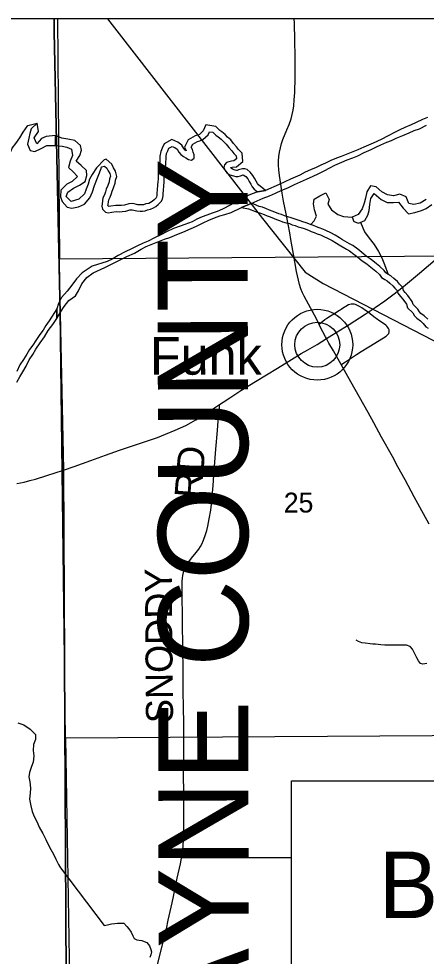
# Model space of a CAD drawing. Extents: x 0 to 34, y 0 to 22.
# Drawn here: x 2.529 to 3.385, y 18.929 to 20.9 of the extents above; entities that cross this region are included whole.
import ezdxf

# ---------------------------------------------------------------- set-up
doc = ezdxf.new("R2010")
doc.units = 0
for name, color, linetype in [('Default', 7, 'Continuous'), ('GM_X_County_Road', 7, 'Continuous'), ('GM_X_County_Text', 7, 'Continuous'), ('GM_X_Major_River', 7, 'Continuous'), ('GM_X_Minor_River', 7, 'Continuous'), ('GM_X_Rail_Line', 7, 'Continuous'), ('GM_X_Section', 7, 'Continuous'), ('GM_X_Section_Text', 7, 'Continuous'), ('GM_X_State_Route', 7, 'Continuous'), ('GM_X_Township_Road', 7, 'Continuous'), ('GM_X_Township_Road_Text', 7, 'Continuous'), ('GM_X_Unincorporated', 7, 'Continuous'), ('GM_X_Unincorporated_Location', 7, 'Continuous'), ('GM_X_Unincorporated_Text', 7, 'Continuous'), ('SH_Cut_Line', 7, 'Continuous'), ('SH_Text', 7, 'Continuous')]:
    doc.layers.add(name, color=color, linetype=linetype)

msp = doc.modelspace()

# ---------------------------------------------------------------- linework, layer by layer
at = {"layer": 'Default'}
for points in [[(2.6032, 20.9), (2.1, 20.9), (2.1, 18.375), (2.6118, 18.3803), (2.6161, 18.3799), (2.6204, 18.3797), (2.6263, 18.3795), (2.6292, 18.3794), (2.6281, 18.8843), (2.6224, 19.9515), (2.6032, 20.8721)], [(3.6061, 20.9), (2.6099, 20.9), (2.614, 20.3953), (3.6114, 20.403), (3.6121, 20.4224)]]:
    msp.add_lwpolyline(points, close=True, dxfattribs=at)
msp.add_lwpolyline([(8.9, 20.9), (2.6032, 20.9), (2.6032, 20.8721), (2.6224, 19.9515), (2.6281, 18.8843)], dxfattribs=at)
at = {"layer": 'GM_X_County_Road'}
for points in [[(3.16, 20.2571), (3.1544, 20.2691), (3.1336, 20.3074), (3.1286, 20.3164), (3.1252, 20.3239), (3.1217, 20.3323), (3.1187, 20.3412), (3.1165, 20.3502), (3.1129, 20.3684), (3.1065, 20.4051), (3.1008, 20.4358), (3.0982, 20.45), (3.0947, 20.4681), (3.0906, 20.4899), (3.0882, 20.5028), (3.0855, 20.5162), (3.0826, 20.5335), (3.077, 20.5704), (3.0755, 20.5824), (3.0749, 20.5918), (3.0749, 20.6011), (3.0754, 20.6104), (3.0767, 20.6196), (3.0786, 20.6286), (3.081, 20.6376), (3.0841, 20.6463), (3.0924, 20.6663), (3.0972, 20.6779), (3.1011, 20.6897), (3.1036, 20.6988), (3.1055, 20.7079), (3.1069, 20.7172), (3.108, 20.7296), (3.1089, 20.7452), (3.1098, 20.7763), (3.1096, 20.8074), (3.1096, 20.8229), (3.1095, 20.8335), (3.1093, 20.8418), (3.1091, 20.8519), (3.109, 20.8603), (3.1085, 20.885), (3.1082, 20.891), (3.108, 20.9)], [(3.1755, 20.2275), (3.1734, 20.2311), (3.1681, 20.2419), (3.1623, 20.2524), (3.16, 20.2571)], [(3.2065, 20.1729), (3.1903, 20.2018), (3.1807, 20.2179), (3.1755, 20.2275)], [(3.3915, 19.8376), (3.372, 19.8729), (3.3601, 19.8947), (3.3409, 19.9303), (3.3259, 19.9577), (3.3141, 19.9794), (3.2914, 20.0201), (3.2751, 20.0501), (3.2633, 20.0718), (3.2453, 20.1043), (3.2271, 20.1368), (3.207, 20.1719), (3.2065, 20.1729)]]:
    msp.add_lwpolyline(points, dxfattribs=at)
at = {"layer": 'GM_X_Major_River'}
for points in [[(3.3878, 20.692), (3.3776, 20.6882), (3.364, 20.682), (3.3538, 20.6771), (3.3406, 20.6713), (3.3296, 20.6663), (3.3183, 20.661), (3.305, 20.6541), (3.2907, 20.6461), (3.274, 20.6384), (3.2642, 20.6342), (3.254, 20.63), (3.2415, 20.6242), (3.2275, 20.6185), (3.2173, 20.6146), (3.2063, 20.6104), (3.1965, 20.6066), (3.1851, 20.602), (3.1738, 20.5966), (3.164, 20.592), (3.1538, 20.5871), (3.142, 20.5825), (3.1307, 20.5771), (3.1197, 20.5714), (3.1095, 20.5671), (3.0997, 20.5625), (3.0883, 20.5568), (3.0759, 20.5514), (3.0474, 20.539)], [(3.2896, 20.6347), (3.3024, 20.6408), (3.3123, 20.6443), (3.3221, 20.6489), (3.3361, 20.6546), (3.3497, 20.66), (3.3603, 20.665), (3.3713, 20.6688), (3.386, 20.6761)], [(3.0173, 20.5118), (3.0302, 20.5171), (3.0426, 20.5225), (3.0559, 20.5278), (3.0684, 20.5336), (3.082, 20.5393), (3.0941, 20.5443), (3.1081, 20.5512), (3.1213, 20.557), (3.1334, 20.5627), (3.1478, 20.5688), (3.158, 20.5738), (3.1708, 20.5803), (3.1825, 20.5864), (3.1935, 20.5922), (3.2079, 20.5983), (3.2192, 20.6033), (3.231, 20.6079), (3.2415, 20.6117), (3.2548, 20.6186), (3.2699, 20.6251), (3.2797, 20.6301), (3.2896, 20.6347)], [(3.0474, 20.539), (3.0305, 20.5359)], [(3.0305, 20.5359), (3.0123, 20.5288), (2.9998, 20.523), (2.9847, 20.515), (2.9745, 20.5089), (2.9571, 20.4997), (2.9458, 20.4947), (2.9352, 20.4909), (2.9242, 20.4867), (2.9144, 20.4836), (2.903, 20.4786), (2.8932, 20.4729), (2.8781, 20.4671), (2.8682, 20.4637), (2.8542, 20.4591), (2.8406, 20.4529), (2.8274, 20.4457), (2.8142, 20.4392), (2.8005, 20.4327), (2.7903, 20.4281), (2.7771, 20.4219), (2.7654, 20.4162), (2.7525, 20.4101), (2.7374, 20.4024), (2.7249, 20.3948), (2.7147, 20.3898)], [(2.7098, 20.3769), (2.7208, 20.3823), (2.7337, 20.3888), (2.7458, 20.3953), (2.7556, 20.3999), (2.7719, 20.4071), (2.7858, 20.4152), (2.7964, 20.4209), (2.8104, 20.4266), (2.821, 20.4312), (2.835, 20.4366), (2.846, 20.4401), (2.8607, 20.4462), (2.8736, 20.4516), (2.8914, 20.4589), (2.9023, 20.4642), (2.9163, 20.4711), (2.9284, 20.4765), (2.9401, 20.4811), (2.9515, 20.4853), (2.9617, 20.4884), (2.9749, 20.4926), (2.9971, 20.5032)], [(2.9971, 20.5032), (3.0173, 20.5118)], [(2.7147, 20.3898), (2.683, 20.3797), (2.6724, 20.3725), (2.6622, 20.366), (2.6501, 20.3534), (2.6403, 20.3401), (2.6305, 20.3275), (2.6185, 20.3138), (2.6122, 20.3011), (2.6085, 20.2898)], [(2.6086, 20.2698), (2.6167, 20.283), (2.6238, 20.2952), (2.634, 20.3074), (2.648, 20.3177), (2.654, 20.328), (2.6611, 20.3424), (2.6717, 20.3561), (2.6853, 20.3661), (2.7098, 20.3769)], [(2.6085, 20.2898), (2.6086, 20.2698)]]:
    msp.add_lwpolyline(points, dxfattribs=at)
at = {"layer": 'GM_X_Minor_River'}
for points in [[(2.3836, 20.5154), (2.3901, 20.5192), (2.3999, 20.5207), (2.4128, 20.528), (2.4188, 20.5382), (2.4241, 20.5512), (2.4275, 20.5622), (2.4347, 20.5743), (2.4434, 20.5846), (2.4555, 20.5964), (2.4695, 20.6036), (2.4812, 20.5999), (2.4945, 20.5984), (2.5047, 20.6064), (2.5096, 20.6163), (2.5149, 20.6277), (2.5221, 20.6376), (2.5308, 20.6494), (2.5376, 20.6615), (2.5478, 20.6752), (2.567, 20.6805)], [(2.567, 20.6805), (2.555, 20.6684), (2.552, 20.6589), (2.5498, 20.649), (2.5471, 20.6361), (2.5525, 20.6229), (2.5624, 20.6206), (2.5756, 20.6271), (2.5877, 20.6336), (2.606, 20.6337)], [(2.6058, 20.6545), (2.5862, 20.6522), (2.5763, 20.648), (2.5669, 20.6373), (2.5611, 20.6495), (2.5698, 20.6628), (2.567, 20.6805)], [(3.0041, 20.5843), (2.9987, 20.5845), (2.9906, 20.582), (2.988, 20.5812), (2.9865, 20.5812), (2.9836, 20.5818), (2.9779, 20.5837), (2.975, 20.5857), (2.974, 20.587), (2.9776, 20.5878), (2.9864, 20.5884), (2.9997, 20.6), (2.9985, 20.6173), (2.9908, 20.625), (2.9866, 20.6307), (2.9798, 20.6374), (2.9744, 20.6452), (2.9678, 20.6512), (2.9625, 20.6564), (2.9555, 20.6621), (2.9511, 20.6651), (2.9429, 20.6733), (2.9217, 20.6766), (2.9163, 20.664), (2.9126, 20.6608), (2.9085, 20.6569), (2.9048, 20.6553), (2.8992, 20.6536), (2.8845, 20.6456), (2.8772, 20.6298), (2.8807, 20.6223), (2.8783, 20.624), (2.8759, 20.6269), (2.8717, 20.6341), (2.8633, 20.6406), (2.8502, 20.6458), (2.8346, 20.637), (2.83, 20.6277), (2.827, 20.6206), (2.8255, 20.6112), (2.8255, 20.6052), (2.8252, 20.5991), (2.8252, 20.5946), (2.8247, 20.5905), (2.8223, 20.5833), (2.8219, 20.5747), (2.8216, 20.5679), (2.8216, 20.5629), (2.8213, 20.5569), (2.8206, 20.5509), (2.8199, 20.5396), (2.8191, 20.5338), (2.8191, 20.5293), (2.8183, 20.5252), (2.8174, 20.5235), (2.8132, 20.5193), (2.8088, 20.5158), (2.8053, 20.5133), (2.8018, 20.5118), (2.7956, 20.5107), (2.7909, 20.5088), (2.7876, 20.5084), (2.7843, 20.5084), (2.7793, 20.5089), (2.7682, 20.5114), (2.7597, 20.5108), (2.7509, 20.5083), (2.7446, 20.5074), (2.7395, 20.507), (2.7326, 20.5074), (2.7223, 20.506), (2.7177, 20.5051), (2.7163, 20.5064), (2.7162, 20.5068), (2.7166, 20.5094), (2.7173, 20.5149), (2.718, 20.5194), (2.7205, 20.5246), (2.7236, 20.5324), (2.7247, 20.5377), (2.7277, 20.5447), (2.7314, 20.554), (2.7321, 20.5607), (2.7347, 20.5681), (2.7323, 20.5794), (2.7281, 20.5864), (2.7245, 20.5941), (2.7121, 20.6044), (2.708, 20.6033)], [(2.7017, 20.5848), (2.7023, 20.5883), (2.7091, 20.5902), (2.714, 20.586), (2.7167, 20.5803), (2.7202, 20.5747), (2.7213, 20.569), (2.7195, 20.5636), (2.7187, 20.5572), (2.7157, 20.5495), (2.7124, 20.5415), (2.7113, 20.5362), (2.7086, 20.5297), (2.7056, 20.5233), (2.7045, 20.5168), (2.7038, 20.5111), (2.7031, 20.5058), (2.705, 20.4993), (2.7111, 20.4936), (2.7164, 20.4917), (2.7244, 20.4933), (2.7331, 20.4945), (2.7396, 20.4941), (2.746, 20.4945), (2.7536, 20.4957), (2.7619, 20.498), (2.7672, 20.4984), (2.7771, 20.4962), (2.7836, 20.4955), (2.7885, 20.4955), (2.7942, 20.4963), (2.7991, 20.4982), (2.8056, 20.4994), (2.8116, 20.5021), (2.8165, 20.5055), (2.8218, 20.5097), (2.8279, 20.5158), (2.8305, 20.5208), (2.832, 20.528), (2.832, 20.533), (2.8327, 20.5383), (2.8334, 20.5497), (2.8341, 20.5558), (2.8345, 20.5626), (2.8344, 20.5676), (2.8348, 20.574), (2.8351, 20.5809), (2.8374, 20.5877), (2.8381, 20.5938), (2.8381, 20.5988), (2.8384, 20.6049), (2.8384, 20.6102), (2.8395, 20.617), (2.8417, 20.6224), (2.8444, 20.6277), (2.8512, 20.6315), (2.8569, 20.6293), (2.8618, 20.6255), (2.8653, 20.6194), (2.8695, 20.6145), (2.8752, 20.6103), (2.8801, 20.6077), (2.8855, 20.6043), (2.8919, 20.6028), (2.8976, 20.607), (2.8972, 20.6139), (2.8956, 20.6196), (2.8937, 20.6249), (2.8914, 20.6298), (2.8944, 20.6363), (2.9043, 20.6417), (2.9092, 20.6432), (2.9156, 20.6459), (2.9213, 20.6512), (2.9269, 20.6562), (2.9296, 20.6623), (2.9368, 20.6612), (2.9429, 20.6551), (2.9478, 20.6517), (2.9539, 20.6468), (2.9589, 20.6419), (2.9646, 20.6366), (2.97, 20.629), (2.9768, 20.6222), (2.981, 20.6165), (2.986, 20.6116), (2.9864, 20.6055), (2.9811, 20.601), (2.9758, 20.6005), (2.9701, 20.5994), (2.9652, 20.5975), (2.9611, 20.5925), (2.9599, 20.5872), (2.9623, 20.5811), (2.9661, 20.5762), (2.9722, 20.572), (2.9802, 20.5694), (2.9851, 20.5683), (2.99, 20.5683), (2.995, 20.5698), (3.0006, 20.5721)], [(2.606, 20.6337), (2.6058, 20.6545)], [(2.708, 20.6033), (2.6917, 20.5868), (2.6826, 20.5723), (2.6773, 20.5628), (2.6744, 20.5521), (2.6706, 20.5419), (2.6665, 20.532), (2.6548, 20.5205), (2.6389, 20.5159), (2.6286, 20.5261), (2.6316, 20.5357), (2.6437, 20.5437), (2.6562, 20.5502), (2.6683, 20.5578), (2.672, 20.5707), (2.6712, 20.581), (2.6598, 20.5916), (2.6495, 20.6007), (2.6571, 20.6125), (2.6604, 20.6239), (2.6581, 20.6337), (2.6464, 20.644), (2.6319, 20.6469), (2.6194, 20.6488), (2.6058, 20.6545)], [(2.606, 20.6337), (2.6199, 20.6321), (2.6294, 20.6298), (2.6392, 20.6261), (2.6415, 20.6128), (2.637, 20.6006), (2.6333, 20.5869), (2.6428, 20.5779), (2.6523, 20.568), (2.6406, 20.5581), (2.6297, 20.552), (2.6172, 20.5394), (2.6161, 20.5253), (2.6196, 20.5155), (2.6306, 20.5037), (2.6405, 20.5015), (2.6541, 20.5042), (2.6666, 20.51), (2.6783, 20.5233), (2.6839, 20.5358), (2.6876, 20.5495), (2.7017, 20.5848)], [(3.0474, 20.539), (3.0327, 20.5506), (3.0304, 20.5536), (3.028, 20.5587), (3.0242, 20.5645), (3.0207, 20.5705), (3.0149, 20.5773), (3.0088, 20.5827), (3.0041, 20.5843)], [(3.0006, 20.5721), (3.006, 20.568), (3.0102, 20.5631), (3.0132, 20.5578), (3.0167, 20.5524), (3.0194, 20.5468), (3.0236, 20.5415), (3.0305, 20.5359)], [(3.0305, 20.5359), (3.0474, 20.539)], [(3.3855, 20.5199), (3.3723, 20.5122), (3.3595, 20.5091), (3.3485, 20.5117), (3.3431, 20.5257), (3.3298, 20.5309), (3.3166, 20.5278), (3.3037, 20.5296), (3.2919, 20.536), (3.2801, 20.5465), (3.2683, 20.5484), (3.2601, 20.5358), (3.2575, 20.5225), (3.2545, 20.5119), (3.2504, 20.5001), (3.2422, 20.4883), (3.2293, 20.4829)], [(3.1419, 20.467), (3.1494, 20.4752), (3.1547, 20.4851), (3.1505, 20.4984), (3.1481, 20.5105), (3.1496, 20.5207), (3.1613, 20.528), (3.1741, 20.5338), (3.181, 20.5198), (3.1784, 20.5103), (3.1864, 20.4982), (3.1997, 20.4884), (3.2115, 20.4843), (3.2295, 20.483)], [(3.2332, 20.4734), (3.2426, 20.4705), (3.2559, 20.4755), (3.2626, 20.4873), (3.2656, 20.4968), (3.2667, 20.5097), (3.2692, 20.5218), (3.2756, 20.5325), (3.2908, 20.5197), (3.3034, 20.5133), (3.3166, 20.5134), (3.3269, 20.5142), (3.3368, 20.5017), (3.3482, 20.49), (3.3614, 20.4928), (3.3751, 20.4967), (3.3853, 20.5009), (3.397, 20.5093)], [(3.0173, 20.5118), (2.9971, 20.5032)], [(2.9971, 20.5032), (3.0113, 20.5003), (3.017, 20.4985), (3.0242, 20.4955), (3.0299, 20.4932), (3.0371, 20.4913), (3.0447, 20.4883), (3.0508, 20.4857), (3.0569, 20.4834), (3.0656, 20.4801), (3.0706, 20.4778), (3.0767, 20.4759), (3.0831, 20.4733), (3.0907, 20.471), (3.0976, 20.4692), (3.1037, 20.4669), (3.1097, 20.465), (3.1162, 20.4628), (3.1219, 20.4609), (3.1284, 20.4587), (3.1375, 20.4553), (3.1432, 20.453), (3.1497, 20.4504), (3.1557, 20.4481), (3.163, 20.4455), (3.1687, 20.4429), (3.179, 20.438), (3.1873, 20.4338), (3.1965, 20.4282), (3.2026, 20.4244), (3.2178, 20.4154), (3.2239, 20.412), (3.2334, 20.4052), (3.2414, 20.3987), (3.2509, 20.3908), (3.2601, 20.3844), (3.2654, 20.3806), (3.2726, 20.3749), (3.2795, 20.3693), (3.2868, 20.3624), (3.291, 20.356), (3.2986, 20.3515), (3.3035, 20.3488), (3.3089, 20.3439), (3.3153, 20.3386), (3.3192, 20.3337), (3.3245, 20.3284), (3.3257, 20.3227), (3.3314, 20.3163), (3.3364, 20.3102), (3.344, 20.2996), (3.3463, 20.2924), (3.3574, 20.2814), (3.3605, 20.2757), (3.3658, 20.2704), (3.373, 20.2651), (3.3791, 20.2595), (3.3845, 20.2523), (3.3894, 20.2496)], [(3.3888, 20.2681), (3.3812, 20.2751), (3.3742, 20.2802), (3.3709, 20.2835), (3.3678, 20.2892), (3.3576, 20.2993), (3.3556, 20.3055), (3.3466, 20.3181), (3.3412, 20.3246), (3.3376, 20.3287), (3.3363, 20.3348), (3.3288, 20.3423), (3.3246, 20.3477), (3.3173, 20.3537), (3.311, 20.3594), (3.3049, 20.3627), (3.3001, 20.3655), (3.2967, 20.3708), (3.288, 20.3789), (3.2807, 20.385), (3.2731, 20.3909), (3.2675, 20.3949), (3.2588, 20.401), (3.2496, 20.4087), (3.2412, 20.4154), (3.2308, 20.4229), (3.2242, 20.4265), (3.2092, 20.4354), (3.2032, 20.4391), (3.1936, 20.4451), (3.1846, 20.4496), (3.1742, 20.4545), (3.1679, 20.4574), (3.1602, 20.4602), (3.1543, 20.4624), (3.148, 20.465), (3.1421, 20.4673), (3.1327, 20.4708), (3.126, 20.4731), (3.1203, 20.475), (3.1138, 20.4773), (3.1078, 20.4791), (3.1015, 20.4815), (3.0943, 20.4834), (3.0874, 20.4855), (3.081, 20.4881), (3.0752, 20.4899), (3.0706, 20.4919), (3.0615, 20.4955), (3.0556, 20.4976), (3.0496, 20.5002), (3.0411, 20.5036), (3.0339, 20.5055), (3.029, 20.5074), (3.0215, 20.5105), (3.0173, 20.5118)], [(3.2293, 20.4829), (3.2332, 20.4734)], [(3.2469, 20.4721), (3.2556, 20.4523), (3.2655, 20.4384), (3.2758, 20.4251), (3.285, 20.4104), (3.2919, 20.3975), (3.2973, 20.3832), (3.3056, 20.3623)], [(2.6085, 20.2898), (2.5922, 20.2648), (2.5858, 20.255), (2.5798, 20.2455), (2.573, 20.2359), (2.5646, 20.2234), (2.5582, 20.2139), (2.5514, 20.2044), (2.5454, 20.1949), (2.5386, 20.1839), (2.531, 20.1721), (2.5243, 20.1584)], [(2.6086, 20.2698), (2.6085, 20.2898)], [(2.5243, 20.136), (2.5311, 20.1474), (2.5372, 20.1577), (2.5439, 20.1695), (2.5507, 20.1831), (2.5579, 20.1938), (2.5647, 20.2056), (2.5738, 20.2185), (2.5825, 20.231), (2.5904, 20.2443), (2.6002, 20.2573), (2.6086, 20.2698)], [(3.3864, 19.5448), (3.3784, 19.5429), (3.373, 19.5448), (3.3688, 19.5501), (3.3654, 19.5562), (3.3592, 19.5691), (3.3562, 19.5745), (3.3516, 19.5802), (3.3435, 19.5828), (3.3378, 19.5828), (3.3302, 19.5832), (3.3248, 19.5829), (3.3184, 19.5832), (3.3123, 19.5829), (3.2985, 19.5829), (3.2901, 19.584), (3.2844, 19.5844), (3.279, 19.5848), (3.2733, 19.5852), (3.2672, 19.5859), (3.2569, 19.5875), (3.25, 19.5878), (3.2432, 19.5905), (3.2382, 19.5932)], [(2.5267, 19.4194), (2.5396, 19.4153), (2.5525, 19.4066), (2.5639, 19.3952), (2.5636, 19.3846), (2.5598, 19.3743), (2.5588, 19.3618), (2.56, 19.3501), (2.5592, 19.3371), (2.5555, 19.3276), (2.551, 19.3155), (2.5499, 19.306), (2.5518, 19.2954), (2.5534, 19.2825), (2.5523, 19.2718), (2.5512, 19.2589), (2.5539, 19.2453), (2.557, 19.2335), (2.5612, 19.2229), (2.567, 19.2108), (2.5712, 19.2006), (2.5792, 19.1873), (2.5853, 19.1741), (2.5903, 19.1642), (2.596, 19.1532), (2.6017, 19.1434), (2.6063, 19.1331), (2.6121, 19.1218), (2.6164, 19.1151)], [(2.6164, 19.1151), (2.7084, 18.9934)], [(2.7084, 18.9934), (2.7149, 18.9949), (2.7233, 18.9968), (2.7305, 18.9979), (2.7359, 18.9983), (2.7427, 18.9987), (2.7492, 18.9983), (2.7561, 18.9918), (2.7603, 18.9865), (2.7649, 18.9793), (2.7684, 18.9717), (2.7714, 18.9664), (2.7768, 18.9633), (2.7818, 18.9629), (2.7875, 18.9618), (2.7925, 18.9599), (2.7978, 18.9576), (2.8035, 18.9511), (2.8062, 18.9435), (2.8074, 18.9382), (2.8066, 18.9317), (2.8044, 18.9264)]]:
    msp.add_lwpolyline(points, dxfattribs=at)
at = {"layer": 'GM_X_Rail_Line'}
msp.add_lwpolyline([(2.7155, 20.9), (2.73, 20.8809), (3.0413, 20.4799), (3.1308, 20.3674), (3.1683, 20.3431), (3.6096, 20.1154), (3.6962, 20.0743), (3.8747, 20.0142), (4.4727, 19.7986), (4.5351, 19.7653), (4.5741, 19.7323), (4.625, 19.6768), (4.956, 19.2976)], dxfattribs=at)
at = {"layer": 'GM_X_Section'}
for points in [[(3.6114, 20.403), (3.6173, 19.4106), (3.6177, 19.3939), (2.6269, 19.3875), (2.614, 20.3953)], [(3.619, 19.2976), (3.6177, 19.3939), (2.6269, 19.3875), (2.6434, 18.3786), (3.6306, 18.3893), (3.6281, 18.5805), (3.1024, 18.5805), (3.1024, 19.2976)]]:
    msp.add_lwpolyline(points, close=True, dxfattribs=at)
at = {"layer": 'GM_X_State_Route'}
for points in [[(3.1755, 20.2275), (3.1871, 20.2346), (3.2231, 20.2575), (3.2572, 20.2791), (3.263, 20.283), (3.2779, 20.2928), (3.2982, 20.307), (3.3181, 20.3218), (3.3376, 20.3372), (3.3711, 20.365), (3.4278, 20.4133)], [(2.6227, 19.9509), (2.6451, 19.9585), (2.6803, 19.9713), (2.7113, 19.9823), (2.7406, 19.9928), (2.7553, 19.9979), (2.7759, 20.0048), (2.7995, 20.0127), (2.8201, 20.0199), (2.8374, 20.0266), (2.8576, 20.0348), (2.869, 20.0397), (2.8802, 20.045), (2.8911, 20.0509), (2.9007, 20.0565), (2.9102, 20.0624), (2.9202, 20.0688), (2.9384, 20.0807), (2.9509, 20.089), (2.9586, 20.0941), (2.9721, 20.103), (2.9957, 20.1181), (3.0264, 20.1372), (3.0724, 20.1655), (3.102, 20.1837), (3.1227, 20.196), (3.1364, 20.2037), (3.1557, 20.2152), (3.1755, 20.2275)], [(2.5248, 19.9226), (2.5399, 19.926), (2.552, 19.9289), (2.5639, 19.9323), (2.5875, 19.9397), (2.6227, 19.9509)]]:
    msp.add_lwpolyline(points, dxfattribs=at)
at = {"layer": 'GM_X_Township_Road'}
for points in [[(3.263, 20.283), (3.2599, 20.2852), (3.2549, 20.2886), (3.2524, 20.2904), (3.2499, 20.2921), (3.2447, 20.2952), (3.242, 20.2966), (3.2392, 20.2979), (3.2364, 20.2991), (3.2335, 20.2999), (3.2305, 20.3002), (3.2274, 20.3002), (3.2244, 20.2995), (3.2216, 20.2983), (3.2163, 20.2953), (3.2137, 20.2936), (3.2067, 20.2887), (3.2043, 20.2871), (3.2018, 20.2856), (3.1967, 20.2824), (3.1839, 20.2746), (3.1763, 20.2698), (3.1723, 20.2668), (3.1647, 20.2609), (3.16, 20.2571)], [(3.2065, 20.1729), (3.2082, 20.174), (3.2155, 20.1788), (3.2282, 20.1872), (3.2385, 20.1938), (3.2488, 20.2004), (3.2776, 20.2181), (3.3011, 20.2326), (3.3035, 20.2345), (3.3055, 20.2368), (3.3065, 20.2384), (3.307, 20.2395), (3.3073, 20.2411), (3.3075, 20.2426), (3.3071, 20.2456), (3.3061, 20.2485), (3.3046, 20.2512), (3.3028, 20.2537), (3.3006, 20.2558), (3.2956, 20.2595), (3.2878, 20.2644), (3.2852, 20.2661), (3.2827, 20.2678), (3.2753, 20.2732), (3.2674, 20.2798), (3.263, 20.283)], [(2.8713, 19.1369), (2.8725, 19.1446), (2.8741, 19.16), (2.875, 19.1754), (2.8759, 19.2063), (2.876, 19.2218), (2.8759, 19.2405), (2.8754, 19.2777), (2.8752, 19.3062), (2.8754, 19.3343), (2.8759, 19.3706), (2.8756, 19.4172), (2.8747, 19.4543), (2.8742, 19.4852), (2.8741, 19.5038), (2.874, 19.5411), (2.8738, 19.5659), (2.8733, 19.5938), (2.8731, 19.6156), (2.8726, 19.6497), (2.8722, 19.6807), (2.8723, 19.6961), (2.8722, 19.7081), (2.8723, 19.7173), (2.8728, 19.7236), (2.8736, 19.7298), (2.8748, 19.736), (2.8757, 19.739), (2.8769, 19.742), (2.8796, 19.7476), (2.8826, 19.7531), (2.886, 19.7584), (2.8918, 19.7658), (2.9015, 19.7777), (2.9071, 19.7851), (2.9104, 19.7903), (2.9133, 19.7956), (2.9172, 19.804), (2.9215, 19.8156), (2.9241, 19.8244), (2.9263, 19.8334), (2.9292, 19.8487), (2.9321, 19.8671), (2.9336, 19.8793), (2.9362, 19.9035), (2.9375, 19.9188), (2.9391, 19.9404), (2.9432, 19.9954), (2.9463, 20.0345), (2.9488, 20.0641), (2.9504, 20.0826), (2.9509, 20.089)], [(2.8147, 18.8856), (2.8169, 18.8962), (2.8226, 18.9204), (2.8278, 18.9415), (2.8317, 18.9566), (2.8391, 18.9867), (2.843, 19.0049), (2.8508, 19.0413), (2.8573, 19.0717), (2.8619, 19.093), (2.8686, 19.1233), (2.871, 19.1355), (2.8713, 19.1369)], [(2.8713, 19.1369), (2.8731, 19.1369), (2.9161, 19.1368), (2.9379, 19.1367), (2.9565, 19.1366), (2.9813, 19.1366), (2.9907, 19.1366), (3, 19.1368), (3.0123, 19.1369), (3.0371, 19.1369), (3.0681, 19.1367), (3.1024, 19.1365)]]:
    msp.add_lwpolyline(points, dxfattribs=at)
at = {"layer": 'GM_X_Unincorporated'}
for radius in [0.0744, 0.0472]:
    msp.add_circle((3.1563, 20.2147), radius, dxfattribs=at)
at = {"layer": 'GM_X_Unincorporated_Location'}
msp.add_line((3.1563, 20.2147), (3.1563, 20.2147), dxfattribs=at)
at = {"layer": 'SH_Cut_Line'}
msp.add_lwpolyline([(2.6032, 20.9), (2.1, 20.9), (2.1, 14.3539), (2.1651, 14.3567), (2.6607, 14.3625), (2.6434, 15.3487), (2.6428, 15.3713), (2.6388, 15.4856), (2.6332, 16.3685), (2.6231, 17.3771), (2.6129, 17.8818), (2.6122, 18.05), (2.6118, 18.3803), (2.6161, 18.3799), (2.6204, 18.3797), (2.6263, 18.3795), (2.6292, 18.3794), (2.6281, 18.8843), (2.6224, 19.9515), (2.6032, 20.8721)], close=True, dxfattribs=at)
msp.add_lwpolyline([(8.9, 20.9), (2.6032, 20.9), (2.6032, 20.8721), (2.6224, 19.9515), (2.6281, 18.8843), (2.6292, 18.3794), (2.6263, 18.3795), (2.6204, 18.3797), (2.6161, 18.3799), (2.6118, 18.3803), (2.6122, 18.05), (2.6129, 17.8818), (2.6231, 17.3771), (2.6332, 16.3685)], dxfattribs=at)
at = {"layer": 'SH_Text'}
msp.add_lwpolyline([(3.1024, 19.2976), (5.3223, 19.2976), (5.3223, 18.5805), (3.1024, 18.5805)], close=True, dxfattribs=at)

# ---------------------------------------------------------------- texts
at = {"layer": 'GM_X_County_Text'}
msp.add_text('WAYNE COUNTY', height=0.189394, rotation=90.0755, dxfattribs=at).set_placement((3.0125, 18.5381))
at = {"layer": 'GM_X_Section_Text'}
msp.add_text('25', height=0.04186, rotation=0, dxfattribs=at).set_placement((3.0858, 19.8618))
at = {"layer": 'GM_X_Township_Road_Text'}
for s, rotation, p in [('RD', 85.2796, (2.9124, 19.8902)), ('SNODDY', 90.4946, (2.8531, 19.4193))]:
    msp.add_text(s, height=0.05682, rotation=rotation, dxfattribs=at).set_placement(p)
at = {"layer": 'GM_X_Unincorporated_Text'}
msp.add_text('Funk', height=0.07898, rotation=0, dxfattribs=at).set_placement((2.8046, 20.1517))
at = {"layer": 'SH_Text'}
msp.add_text('BEGIN ACQUISTION', height=0.14, dxfattribs=at).set_placement((3.2855, 19.0091))

doc.saveas('drawing.dxf')
